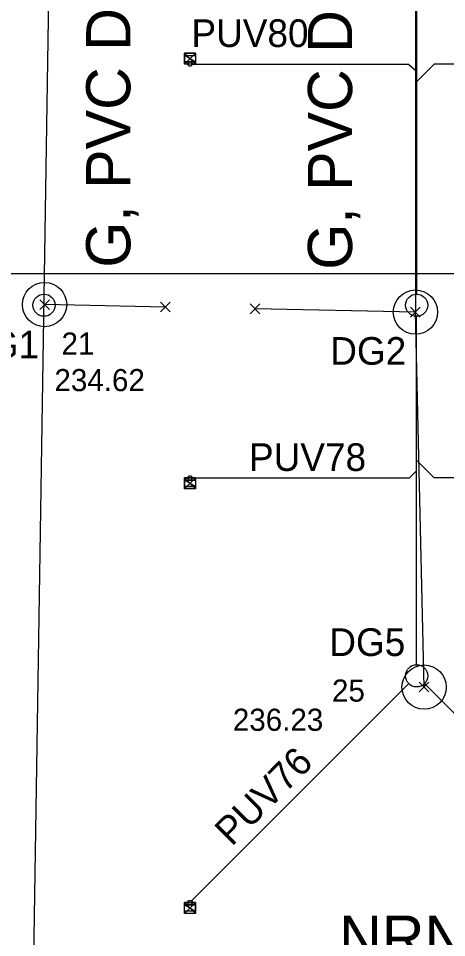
# Model space of a CAD drawing. Extents: x -264234 to -263604, y -1242346 to -1242049.
# Drawn here: x -263944.61 to -263925.24, y -1242233.35 to -1242191.79 of the extents above; entities that cross this region are included whole.
import ezdxf

# ---------------------------------------------------------------- set-up
doc = ezdxf.new("R2010")
doc.units = 0
for name, color, linetype in [('KFA_BODY_CISLO', 7, 'Continuous'), ('KFA_BODY_SYMBOL', 7, 'Continuous'), ('KFA_BODY_VYSKA', 7, 'Continuous'), ('KFA_DAZDOVA_KANALIZACIA_retencna_nadrz_popis', 7, 'Continuous'), ('KFA_DAZDOVA_KANALIZACIA_vetva_G', 7, 'Continuous'), ('KFA_DAZDOVA_KANALIZACIA_vetva_G_popis', 7, 'Continuous'), ('KFA_JESTV_IS_DSP_-_KANAL_DAZD', 7, 'Continuous'), ('KFA_SITUACIA_DSP', 7, 'Continuous'), ('KFA_SO_40-2-II_DK_PRIPOJKY_UV_PROJEKT', 7, 'Continuous'), ('KFA_SO_40-2-II_DK_PRIPOJKY_UV_PROJEKT_popis', 7, 'Continuous'), ('KFA_SO_40-2-II_DK_UV_PROJEKT', 7, 'Continuous')]:
    doc.layers.add(name, color=color, linetype=linetype)

msp = doc.modelspace()

# ---------------------------------------------------------------- linework, layer by layer
at = {"layer": 'KFA_BODY_SYMBOL'}
for p, q in [((-263943.641, -1242204.948), (-263943.199, -1242204.506)), ((-263943.199, -1242204.948), (-263943.641, -1242204.506)), ((-263938.179, -1242205.058), (-263937.737, -1242204.616)), ((-263937.737, -1242205.058), (-263938.179, -1242204.616)), ((-263934.124, -1242205.14), (-263933.682, -1242204.698)), ((-263933.682, -1242205.14), (-263934.124, -1242204.698)), ((-263926.867, -1242205.287), (-263926.425, -1242204.845)), ((-263926.425, -1242205.287), (-263926.867, -1242204.845)), ((-263926.476, -1242222.24), (-263926.034, -1242221.798)), ((-263926.034, -1242222.24), (-263926.476, -1242221.798))]:
    msp.add_line(p, q, dxfattribs=at)
at = {"layer": 'KFA_DAZDOVA_KANALIZACIA_vetva_G'}
for points in [[(-263926.523, -1242108.42), (-263926.639, -1242155.082), (-263926.646, -1242205.066)], [(-263937.958, -1242204.837), (-263943.42, -1242204.727)], [(-263926.255, -1242222.019), (-263926.646, -1242205.066), (-263933.903, -1242204.919)]]:
    msp.add_lwpolyline(points, dxfattribs=at)
for centre in [(-263943.42, -1242204.727), (-263926.646, -1242205.066), (-263926.255, -1242222.019)]:
    msp.add_circle(centre, 1, dxfattribs=at)
at = {"layer": 'KFA_JESTV_IS_DSP_-_KANAL_DAZD'}
msp.add_line((-263943.946, -1242236.311), (-263943.136, -1242185.245), dxfattribs=at)
at = {"layer": 'KFA_SITUACIA_DSP'}
for p, q in [((-263926.593, -1242155.252), (-263926.593, -1242204.252)), ((-263937.093, -1242193.752), (-263937.093, -1242193.462)), ((-263937.093, -1242193.462), (-263936.593, -1242193.462)), ((-263936.593, -1242193.752), (-263937.093, -1242193.462)), ((-263936.593, -1242193.752), (-263937.093, -1242193.462)), ((-263937.093, -1242193.462), (-263937.093, -1242193.752)), ((-263936.593, -1242193.462), (-263936.593, -1242193.752)), ((-263936.593, -1242193.752), (-263937.093, -1242193.752)), ((-263937.093, -1242193.752), (-263936.593, -1242193.752)), ((-263936.743, -1242193.852), (-263926.953, -1242193.852)), ((-263926.953, -1242193.852), (-263926.593, -1242194.178)), ((-263925.798, -1242193.852), (-263926.593, -1242194.648)), ((-263920.944, -1242193.852), (-263925.798, -1242193.852)), ((-263924.893, -1242203.332), (-263958.097, -1242203.332)), ((-263926.593, -1242221.011), (-263926.593, -1242205.252)), ((-263925.798, -1242212.562), (-263926.593, -1242211.767)), ((-263926.919, -1242212.562), (-263926.593, -1242212.237)), ((-263937.093, -1242212.952), (-263937.093, -1242212.662)), ((-263937.093, -1242212.662), (-263936.593, -1242212.662)), ((-263936.593, -1242212.952), (-263937.093, -1242212.662)), ((-263936.593, -1242212.952), (-263937.093, -1242212.662)), ((-263937.093, -1242212.662), (-263937.093, -1242212.952)), ((-263936.743, -1242212.562), (-263926.919, -1242212.562)), ((-263936.593, -1242212.662), (-263936.593, -1242212.952)), ((-263916.443, -1242212.562), (-263925.798, -1242212.562)), ((-263936.593, -1242212.952), (-263937.093, -1242212.952)), ((-263937.093, -1242212.952), (-263936.593, -1242212.952)), ((-263936.772, -1242231.691), (-263926.947, -1242221.865)), ((-263916.414, -1242231.691), (-263926.24, -1242221.865)), ((-263937.093, -1242231.862), (-263936.593, -1242231.862)), ((-263937.093, -1242232.152), (-263937.093, -1242231.862)), ((-263937.093, -1242231.862), (-263936.593, -1242232.152)), ((-263937.093, -1242231.862), (-263936.593, -1242232.152)), ((-263936.593, -1242231.862), (-263937.093, -1242231.862)), ((-263936.593, -1242231.862), (-263936.593, -1242232.152)), ((-263936.593, -1242232.152), (-263936.593, -1242231.862)), ((-263936.593, -1242232.152), (-263937.093, -1242232.152))]:
    msp.add_line(p, q, dxfattribs=at)
for centre, radius in [((-263936.843, -1242193.852), 0.1), ((-263943.445, -1242204.752), 0.5), ((-263926.593, -1242204.752), 0.5), ((-263936.843, -1242212.562), 0.1), ((-263926.593, -1242221.511), 0.5), ((-263936.843, -1242231.762), 0.1)]:
    msp.add_circle(centre, radius, dxfattribs=at)
at = {"layer": 'KFA_SO_40-2-II_DK_PRIPOJKY_UV_PROJEKT'}
for points in [[(-263936.743, -1242193.852), (-263926.953, -1242193.852), (-263926.593, -1242194.178)], [(-263920.944, -1242193.852), (-263925.798, -1242193.852), (-263926.593, -1242194.648)], [(-263916.443, -1242212.562), (-263925.798, -1242212.562), (-263926.593, -1242211.767)], [(-263936.743, -1242212.562), (-263926.919, -1242212.562), (-263926.593, -1242212.237)], [(-263936.772, -1242231.691), (-263926.947, -1242221.865)], [(-263916.414, -1242231.691), (-263926.24, -1242221.865)]]:
    msp.add_lwpolyline(points, dxfattribs=at)
at = {"layer": 'KFA_SO_40-2-II_DK_UV_PROJEKT'}
for points in [[(-263937.093, -1242193.857), (-263937.093, -1242193.357), (-263936.593, -1242193.357), (-263936.593, -1242193.857), (-263937.093, -1242193.857), (-263936.593, -1242193.357), (-263937.093, -1242193.357), (-263936.593, -1242193.857)], [(-263937.093, -1242213.057), (-263937.093, -1242212.557), (-263936.593, -1242212.557), (-263936.593, -1242213.057), (-263937.093, -1242213.057), (-263936.593, -1242212.557), (-263937.093, -1242212.557), (-263936.593, -1242213.057)], [(-263937.093, -1242232.257), (-263937.093, -1242231.757), (-263936.593, -1242231.757), (-263936.593, -1242232.257), (-263937.093, -1242232.257), (-263936.593, -1242231.757), (-263937.093, -1242231.757), (-263936.593, -1242232.257)]]:
    msp.add_lwpolyline(points, dxfattribs=at)

# ---------------------------------------------------------------- texts
at = {"layer": 'KFA_BODY_CISLO'}
for s, p in [('21', (-263942.654, -1242206.987)), ('25', (-263930.421, -1242222.677))]:
    msp.add_text(s, height=1, dxfattribs=at).set_placement(p)
at = {"layer": 'KFA_BODY_VYSKA'}
for s, p in [('234.62', (-263942.975, -1242208.64)), ('236.23', (-263934.905, -1242223.997))]:
    msp.add_text(s, height=1, dxfattribs=at).set_placement(p)
at = {"layer": 'KFA_DAZDOVA_KANALIZACIA_retencna_nadrz_popis'}
msp.add_text('NRN, PVC DN600 - 8,17 m', height=2, dxfattribs=at).set_placement((-263930.102, -1242234.349))
at = {"layer": 'KFA_DAZDOVA_KANALIZACIA_vetva_G_popis'}
for s, p in [('G, PVC DN300 - 5,46 m', (-263939.541, -1242203.058)), ('G, PVC DN300 - 7,26 m', (-263929.511, -1242203.15))]:
    msp.add_text(s, height=2, rotation=90, dxfattribs=at).set_placement(p)
for s, p in [('DG1', (-263947.106, -1242207.158)), ('DG2', (-263930.499, -1242207.446)), ('DG5', (-263930.542, -1242220.614))]:
    msp.add_text(s, height=1.25, dxfattribs=at).set_placement(p)
at = {"layer": 'KFA_SO_40-2-II_DK_PRIPOJKY_UV_PROJEKT_popis'}
for s, p in [('PUV80', (-263936.777, -1242193.079)), ('PUV78', (-263934.174, -1242212.248))]:
    msp.add_text(s, height=1.25, dxfattribs=at).set_placement(p)
msp.add_text('PUV76', height=1.25, rotation=45.0029, dxfattribs=at).set_placement((-263934.955, -1242229.252))

doc.saveas('drawing.dxf')
